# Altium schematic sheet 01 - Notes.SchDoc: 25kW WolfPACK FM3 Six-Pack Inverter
size 431 x 279 mm; Date: 07/2023; DocumentNumber: CRD25DA12N-FMC; Revision: 1.1; SheetNumber: 1; SheetTotal: 8; SheetSize: B
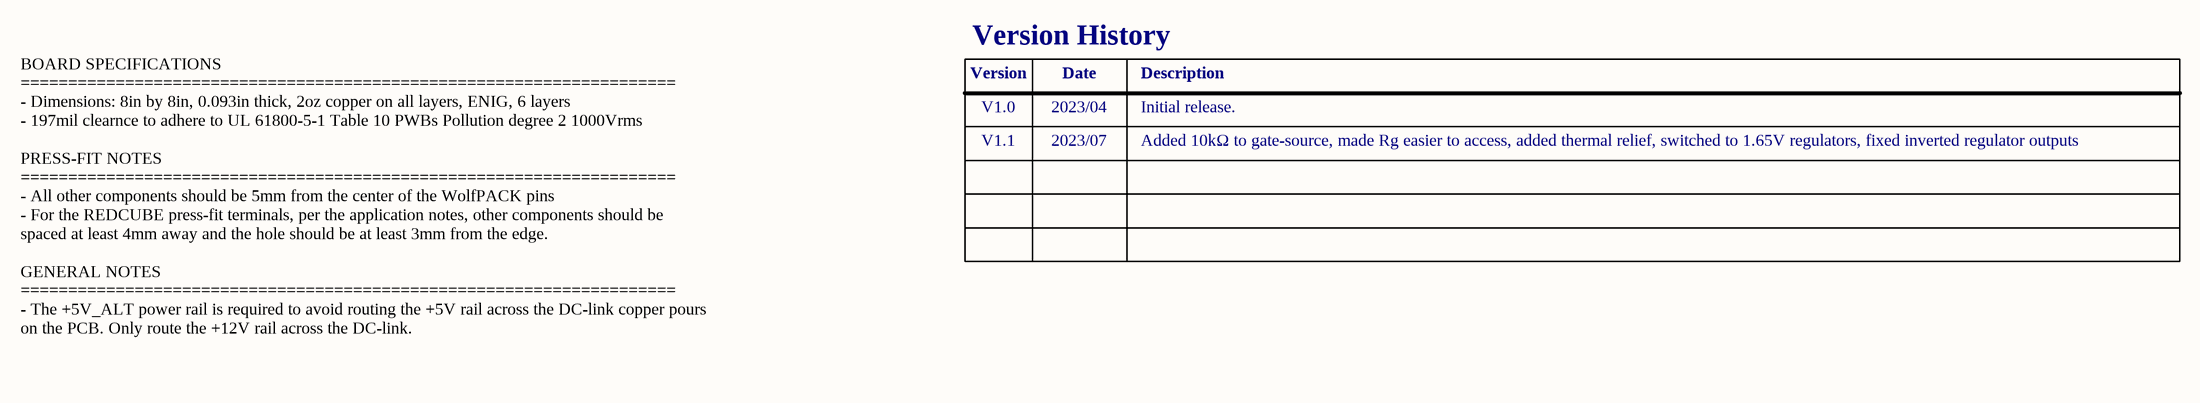
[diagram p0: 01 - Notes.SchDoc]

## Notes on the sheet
- Version History
- Version
- Date
- Description
- V1.0
- V1.1
- 2023/04
- 2023/07
- Initial release.
- Added 10kΩ to gate-source, made Rg easier to access, added thermal relief, switched to 1.65V regulators, fixed inverted regulator outputs
- BOARD SPECIFICATIONS
  =====================================================================
  - Dimensions: 8in by 8in, 0.093in thick, 2oz copper on all layers, ENIG, 6 layers
  - 197mil clearnce to adhere to UL 61800-5-1 Table 10 PWBs Pollution degree 2 1000Vrms
  PRESS-FIT NOTES
  =====================================================================
  - All other components should be 5mm from the center of the WolfPACK pins
  - For the REDCUBE press-fit terminals, per the application notes, other components should be spaced at least 4mm away and the hole should be at least 3mm from the edge.
  GENERAL NOTES
  =====================================================================
  - The +5V_ALT power rail is required to avoid routing the +5V rail across the DC-link copper pours on the PCB. Only route the +12V rail across the DC-link.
